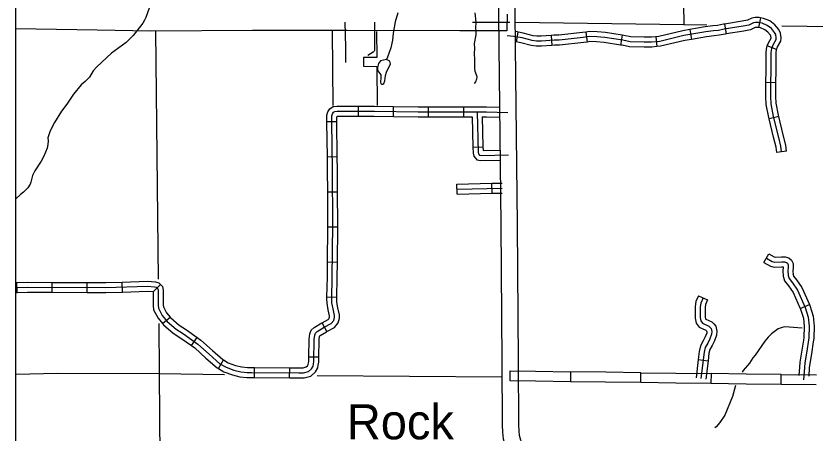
# Model space of a CAD drawing. Extents: x 1373862 to 1376999, y 1168398 to 1170455.
# Drawn here: x 1374675.3 to 1374915.6, y 1169193.7 to 1169319 of the extents above; entities that cross this region are included whole.
import ezdxf

# ---------------------------------------------------------------- set-up
doc = ezdxf.new("R2010")
doc.units = 0
for name, color, linetype in [('Level 10', 7, 'Continuous'), ('Level 25', 7, 'Continuous'), ('Level 31', 7, 'Continuous'), ('Level 32', 7, 'Continuous'), ('Level 34', 7, 'Continuous'), ('Level 35', 7, 'Continuous'), ('Level 45', 7, 'Continuous'), ('Level 5', 7, 'Continuous'), ('Level 6', 7, 'Continuous'), ('R_Draft', 7, 'Continuous')]:
    doc.layers.add(name, color=color, linetype=linetype)

msp = doc.modelspace()

# ---------------------------------------------------------------- linework, layer by layer
at = {"layer": 'Level 10'}
msp.add_line((1374823, 1169319.56), (1374822.98, 1169314.56), dxfattribs=at)
for points in [[(1374818.87, 1169418.56), (1374818.98, 1169414.74), (1374819.85, 1169391.37), (1374819.94, 1169378.37), (1374820.36, 1169342.16), (1374820.46, 1169319.79), (1374820.56, 1169309.87), (1374821.13, 1169256.36), (1374821.44, 1169215.18), (1374821.52, 1169196.04), (1374821.61, 1169193.92), (1374821.82, 1169191.93), (1374822.39, 1169189.89), (1374822.82, 1169188.87), (1374823.6, 1169187.49), (1374824.34, 1169186.4), (1374825.12, 1169185.51), (1374839.88, 1169172.1)], [(1374843.25, 1169175.79), (1374828.68, 1169189.03), (1374828.3, 1169189.47), (1374827.85, 1169190.12), (1374827.32, 1169191.07), (1374827.12, 1169191.55), (1374826.75, 1169192.87), (1374826.6, 1169194.28), (1374826.52, 1169196.16), (1374826.44, 1169215.21), (1374826.13, 1169256.4), (1374825.56, 1169309.92), (1374825.46, 1169319.83), (1374825.36, 1169342.2), (1374824.94, 1169378.41), (1374824.85, 1169391.48), (1374823.98, 1169414.91), (1374823.86, 1169418.72)], [(1374822.98, 1169314.56), (1374808.75, 1169314.61), (1374774.93, 1169314.7), (1374746.42, 1169314.67), (1374715.92, 1169314.49), (1374699.79, 1169314.74), (1374675.34, 1169315.16)]]:
    msp.add_lwpolyline(points, dxfattribs=at)
at = {"layer": 'Level 31'}
for p, q in [((1374823.94, 1169209.31), (1374823.98, 1169212.31)), ((1374842.11, 1169212.08), (1374842.07, 1169209.08)), ((1374863.19, 1169208.8), (1374863.23, 1169211.8)), ((1374884.34, 1169211.53), (1374884.31, 1169208.53)), ((1374905.42, 1169208.26), (1374905.46, 1169211.26)), ((1374884.31, 1169208.53), (1374884.31, 1169208.53))]:
    msp.add_line(p, q, dxfattribs=at)
for points in [[(1374823.98, 1169212.31), (1374831.55, 1169212.21)], [(1374831.55, 1169212.21), (1374842.11, 1169212.08)], [(1374852.67, 1169211.94), (1374842.11, 1169212.08)], [(1374863.23, 1169211.8), (1374852.67, 1169211.94)], [(1374863.23, 1169211.8), (1374873.79, 1169211.67)], [(1374873.79, 1169211.67), (1374884.34, 1169211.53)], [(1374894.9, 1169211.39), (1374884.34, 1169211.53)], [(1374905.46, 1169211.26), (1374894.9, 1169211.39)], [(1374831.51, 1169209.21), (1374823.94, 1169209.31)], [(1374842.07, 1169209.08), (1374831.51, 1169209.21)], [(1374852.63, 1169208.94), (1374842.07, 1169209.08)], [(1374905.46, 1169211.26), (1374916.02, 1169211.12)], [(1374863.19, 1169208.8), (1374852.63, 1169208.94)], [(1374873.75, 1169208.67), (1374863.19, 1169208.8)], [(1374884.31, 1169208.53), (1374873.75, 1169208.67)], [(1374894.86, 1169208.39), (1374884.31, 1169208.53)], [(1374905.42, 1169208.26), (1374894.86, 1169208.39)], [(1374915.98, 1169208.12), (1374905.42, 1169208.26)]]:
    msp.add_lwpolyline(points, dxfattribs=at)
at = {"layer": 'Level 32'}
for p, q in [((1374899.22, 1169318.51), (1374898.61, 1169315.57)), ((1374877.93, 1169314.97), (1374878.45, 1169312.01)), ((1374888.38, 1169316.61), (1374888.86, 1169313.65)), ((1374826.27, 1169314.21), (1374825.69, 1169311.27)), ((1374836.26, 1169313.21), (1374836.5, 1169310.22)), ((1374846.68, 1169314.19), (1374847.09, 1169311.22)), ((1374857.6, 1169313.29), (1374857.15, 1169310.32)), ((1374867.73, 1169312.82), (1374868, 1169309.84)), ((1374904.06, 1169308.99), (1374901.25, 1169310.04)), ((1374903.85, 1169298.97), (1374900.85, 1169299)), ((1374778.29, 1169288.91), (1374778.3, 1169291.91)), ((1374788.83, 1169288.82), (1374788.87, 1169291.82)), ((1374799.4, 1169288.71), (1374799.42, 1169291.71)), ((1374809.97, 1169288.68), (1374809.97, 1169291.68)), ((1374904.69, 1169288.86), (1374901.78, 1169288.15)), ((1374771.84, 1169287.21), (1374768.84, 1169287.21)), ((1374812.75, 1169279.59), (1374815.75, 1169279.66)), ((1374771.96, 1169276.67), (1374768.96, 1169276.63)), ((1374907.05, 1169278.4), (1374904.08, 1169278.02)), ((1374807.98, 1169265.48), (1374807.91, 1169268.48)), ((1374818.54, 1169265.74), (1374818.47, 1169268.74)), ((1374772.06, 1169266.1), (1374769.06, 1169266.08)), ((1374772.12, 1169255.52), (1374769.12, 1169255.55)), ((1374772.01, 1169244.96), (1374769.01, 1169244.99)), ((1374675.7, 1169235.9), (1374675.6, 1169238.9)), ((1374686.2, 1169235.96), (1374686.22, 1169238.96)), ((1374696.76, 1169235.9), (1374696.77, 1169238.9)), ((1374707.37, 1169236.03), (1374707.28, 1169239.03)), ((1374716.68, 1169236.16), (1374718.8, 1169238.28)), ((1374771.79, 1169234.38), (1374768.79, 1169234.46)), ((1374719.43, 1169226.55), (1374721.72, 1169228.49)), ((1374768.77, 1169224.16), (1374767.4, 1169226.83)), ((1374728.1, 1169219.93), (1374729.83, 1169222.38)), ((1374766.43, 1169216.44), (1374763.43, 1169216.47)), ((1374736.24, 1169213.01), (1374737.73, 1169215.62)), ((1374747.07, 1169210.34), (1374747.08, 1169213.34)), ((1374757.63, 1169210.3), (1374757.64, 1169213.3))]:
    msp.add_line(p, q, dxfattribs=at)
for points in [[(1374899.22, 1169318.51), (1374898.77, 1169318.6), (1374897.57, 1169318.6), (1374896.63, 1169318.4), (1374895.25, 1169317.75), (1374893.74, 1169317.48), (1374888.38, 1169316.61)], [(1374904.06, 1169308.99), (1374904.33, 1169309.72), (1374905.36, 1169311.49), (1374905.45, 1169312.52), (1374905.26, 1169313.92), (1374904.71, 1169314.94), (1374903.53, 1169316.39), (1374902, 1169317.54), (1374900.11, 1169318.32), (1374899.22, 1169318.51)], [(1374905.57, 1169278.21), (1374905.35, 1169279.93), (1374904.6, 1169282.93), (1374903.15, 1169288.87), (1374902.44, 1169292.62), (1374902.35, 1169294.82), (1374902.35, 1169298.96), (1374902.4, 1169302.66), (1374902.4, 1169308.03), (1374902.57, 1169309.31), (1374902.97, 1169310.37), (1374903.89, 1169311.95), (1374903.94, 1169312.48), (1374903.81, 1169313.45), (1374903.45, 1169314.11), (1374902.49, 1169315.3), (1374901.25, 1169316.22), (1374899.67, 1169316.88), (1374898.61, 1169317.1), (1374897.73, 1169317.1), (1374897.11, 1169316.97), (1374895.71, 1169316.31), (1374893.99, 1169316), (1374888.31, 1169315.08), (1374886.55, 1169314.73), (1374885.1, 1169314.55), (1374882.76, 1169314.29), (1374876.2, 1169313.14), (1374868.9, 1169311.42), (1374866.48, 1169311.2), (1374864.23, 1169311.16), (1374860, 1169311.25), (1374857.85, 1169311.73), (1374852.39, 1169312.57), (1374850.01, 1169312.74), (1374847.81, 1169312.83), (1374845.87, 1169312.57), (1374838.7, 1169311.78), (1374837.16, 1169311.78), (1374833.33, 1169311.47), (1374831.83, 1169311.47), (1374830.55, 1169311.64), (1374827.52, 1169312.44), (1374825.05, 1169312.92), (1374823.03, 1169313.1)], [(1374877.93, 1169314.97), (1374875.9, 1169314.61), (1374868.66, 1169312.91), (1374867.73, 1169312.82)], [(1374888.38, 1169316.61), (1374888.04, 1169316.55), (1374886.31, 1169316.21), (1374884.92, 1169316.04), (1374882.55, 1169315.77), (1374877.93, 1169314.97)], [(1374898.61, 1169315.57), (1374898.46, 1169315.6), (1374897.89, 1169315.6), (1374897.6, 1169315.54), (1374896.16, 1169314.87), (1374894.24, 1169314.52), (1374888.86, 1169313.65)], [(1374901.25, 1169310.04), (1374901.61, 1169311.01), (1374902.43, 1169312.41), (1374902.43, 1169312.44), (1374902.36, 1169312.98), (1374902.2, 1169313.28), (1374901.44, 1169314.21), (1374900.5, 1169314.91), (1374899.22, 1169315.44), (1374898.61, 1169315.57)], [(1374836.26, 1169313.21), (1374833.27, 1169312.97), (1374831.93, 1169312.97), (1374830.85, 1169313.12), (1374827.85, 1169313.9), (1374825.52, 1169314.36)], [(1374846.68, 1169314.19), (1374845.69, 1169314.06), (1374838.61, 1169313.28), (1374837.1, 1169313.28), (1374836.26, 1169313.21)], [(1374857.6, 1169313.29), (1374852.56, 1169314.06), (1374850.1, 1169314.24), (1374847.74, 1169314.34), (1374846.68, 1169314.19)], [(1374867.73, 1169312.82), (1374866.39, 1169312.7), (1374864.23, 1169312.66), (1374860.19, 1169312.74), (1374858.13, 1169313.21), (1374857.6, 1169313.29)], [(1374888.86, 1169313.65), (1374888.58, 1169313.6), (1374886.79, 1169313.24), (1374885.27, 1169313.06), (1374882.98, 1169312.8), (1374878.45, 1169312.01)], [(1374836.5, 1169310.22), (1374833.39, 1169309.97), (1374831.73, 1169309.97), (1374830.26, 1169310.17), (1374827.18, 1169310.97), (1374825.69, 1169311.27)], [(1374847.09, 1169311.22), (1374846.06, 1169311.08), (1374838.78, 1169310.28), (1374837.22, 1169310.28), (1374836.5, 1169310.22)], [(1374857.15, 1169310.32), (1374852.22, 1169311.08), (1374849.93, 1169311.25), (1374847.88, 1169311.33), (1374847.09, 1169311.22)], [(1374868, 1169309.84), (1374866.56, 1169309.7), (1374864.23, 1169309.66), (1374859.82, 1169309.75), (1374857.57, 1169310.26), (1374857.15, 1169310.32)], [(1374878.45, 1169312.01), (1374876.5, 1169311.67), (1374869.14, 1169309.94), (1374868, 1169309.84)], [(1374900.85, 1169299), (1374900.9, 1169302.67), (1374900.9, 1169308.13), (1374901.11, 1169309.68), (1374901.25, 1169310.04)], [(1374903.85, 1169298.97), (1374903.9, 1169302.65), (1374903.9, 1169307.93), (1374904.04, 1169308.94), (1374904.06, 1169308.99)], [(1374901.78, 1169288.15), (1374901.68, 1169288.56), (1374900.95, 1169292.45), (1374900.85, 1169294.79), (1374900.85, 1169298.97), (1374900.85, 1169299)], [(1374904.69, 1169288.86), (1374904.61, 1169289.19), (1374903.94, 1169292.79), (1374903.85, 1169294.85), (1374903.85, 1169298.95), (1374903.85, 1169298.97)], [(1374768.84, 1169287.21), (1374768.84, 1169289.2), (1374769.15, 1169290.26), (1374769.7, 1169291.17), (1374770.71, 1169291.82), (1374771.83, 1169291.94), (1374778.3, 1169291.91)], [(1374778.3, 1169291.91), (1374783.11, 1169291.9), (1374788.87, 1169291.82)], [(1374788.87, 1169291.82), (1374796.28, 1169291.73), (1374799.42, 1169291.71)], [(1374799.42, 1169291.71), (1374804.39, 1169291.68), (1374809.97, 1169291.68)], [(1374809.97, 1169291.68), (1374816.81, 1169291.68), (1374820.75, 1169291.59)], [(1374675.34, 1169237.39), (1374678.75, 1169237.5), (1374702.33, 1169237.37), (1374714.86, 1169237.77), (1374717, 1169237.64), (1374717.49, 1169237.47), (1374717.98, 1169236.98), (1374718.11, 1169236.46), (1374718.11, 1169232.08), (1374718.18, 1169231.17), (1374719.31, 1169229), (1374720.82, 1169227.23), (1374723.47, 1169224.89), (1374725.74, 1169223.44), (1374730.02, 1169220.41), (1374733.42, 1169217.33), (1374736.67, 1169214.5), (1374738.51, 1169213.44), (1374740.85, 1169212.56), (1374742.94, 1169212.04), (1374744.84, 1169211.82), (1374746.14, 1169211.84), (1374760.39, 1169211.79), (1374761.84, 1169211.79), (1374763.3, 1169212.14), (1374764.21, 1169212.95), (1374764.65, 1169213.76), (1374764.75, 1169214.33), (1374764.92, 1169215.14), (1374764.99, 1169221.75), (1374765.17, 1169223.08), (1374765.39, 1169223.72), (1374765.88, 1169224.22), (1374768, 1169225.45), (1374770.16, 1169226.56), (1374770.88, 1169227.44), (1374771.12, 1169228.38), (1374771.12, 1169229.04), (1374770.68, 1169230.97), (1374770.36, 1169232.82), (1374770.29, 1169234.08), (1374770.46, 1169240.46), (1374770.63, 1169256.39), (1374770.51, 1169272.81), (1374770.34, 1169287.11), (1374770.34, 1169288.98), (1374770.53, 1169289.65), (1374770.8, 1169290.09), (1374771.22, 1169290.36), (1374771.91, 1169290.44), (1374783.1, 1169290.4), (1374796.26, 1169290.23), (1374804.39, 1169290.18), (1374816.79, 1169290.18), (1374823.27, 1169290.03)], [(1374771.84, 1169287.21), (1374771.84, 1169288.77), (1374771.88, 1169288.93), (1374771.99, 1169288.94), (1374778.29, 1169288.91)], [(1374778.29, 1169288.91), (1374783.09, 1169288.9), (1374788.83, 1169288.82)], [(1374788.83, 1169288.82), (1374796.25, 1169288.73), (1374799.4, 1169288.71)], [(1374799.4, 1169288.71), (1374804.38, 1169288.68), (1374809.97, 1169288.68)], [(1374809.97, 1169288.68), (1374812.54, 1169288.68)], [(1374812.54, 1169288.68), (1374812.75, 1169279.59)], [(1374814, 1169290.18), (1374814.29, 1169277.97), (1374814.39, 1169277.59), (1374814.72, 1169277.21), (1374815.25, 1169277.11), (1374823.41, 1169277.25)], [(1374815.54, 1169288.68), (1374815.75, 1169279.66)], [(1374815.54, 1169288.68), (1374816.77, 1169288.68), (1374820.78, 1169288.59)], [(1374907.05, 1169278.4), (1374906.82, 1169280.21), (1374906.05, 1169283.29), (1374904.69, 1169288.86)], [(1374768.96, 1169276.63), (1374768.84, 1169287.1), (1374768.84, 1169287.21)], [(1374771.96, 1169276.67), (1374771.84, 1169287.12), (1374771.84, 1169287.21)], [(1374904.08, 1169278.02), (1374903.87, 1169279.65), (1374903.14, 1169282.57), (1374901.78, 1169288.15)], [(1374812.75, 1169279.59), (1374812.79, 1169277.77), (1374813.02, 1169276.87), (1374813.94, 1169275.82), (1374815.12, 1169275.61), (1374820.92, 1169275.71)], [(1374815.75, 1169279.66), (1374815.78, 1169278.62), (1374820.89, 1169278.71)], [(1374769.06, 1169266.08), (1374769.01, 1169272.79), (1374768.96, 1169276.63)], [(1374772.06, 1169266.1), (1374772.01, 1169272.82), (1374771.96, 1169276.67)], [(1374807.91, 1169268.48), (1374818.47, 1169268.74)], [(1374807.95, 1169266.98), (1374821.53, 1169267.31)], [(1374818.47, 1169268.74), (1374821.49, 1169268.81)], [(1374769.12, 1169255.55), (1374769.13, 1169256.4), (1374769.06, 1169266.08)], [(1374772.12, 1169255.52), (1374772.13, 1169256.39), (1374772.06, 1169266.1)], [(1374807.98, 1169265.48), (1374818.54, 1169265.74)], [(1374818.54, 1169265.74), (1374821.57, 1169265.81)], [(1374769.01, 1169244.99), (1374769.12, 1169255.55)], [(1374772.01, 1169244.96), (1374772.12, 1169255.52)], [(1374768.79, 1169234.46), (1374768.96, 1169240.49), (1374769.01, 1169244.99)], [(1374771.79, 1169234.38), (1374771.96, 1169240.43), (1374772.01, 1169244.96)], [(1374675.34, 1169238.89), (1374675.6, 1169238.9)], [(1374675.6, 1169238.9), (1374678.73, 1169239), (1374686.22, 1169238.96)], [(1374686.22, 1169238.96), (1374696.77, 1169238.9)], [(1374696.77, 1169238.9), (1374702.31, 1169238.87), (1374707.28, 1169239.03)], [(1374707.28, 1169239.03), (1374714.88, 1169239.27), (1374717.3, 1169239.13), (1374718.31, 1169238.77), (1374718.8, 1169238.28)], [(1374718.8, 1169238.28), (1374719.35, 1169237.74), (1374719.61, 1169236.64), (1374719.61, 1169232.14), (1374719.65, 1169231.59), (1374720.57, 1169229.84), (1374721.72, 1169228.49)], [(1374675.34, 1169235.89), (1374675.7, 1169235.9)], [(1374675.7, 1169235.9), (1374678.77, 1169236), (1374686.2, 1169235.96)], [(1374686.2, 1169235.96), (1374696.76, 1169235.9)], [(1374696.76, 1169235.9), (1374702.35, 1169235.87), (1374707.37, 1169236.03)], [(1374707.37, 1169236.03), (1374714.84, 1169236.27), (1374716.68, 1169236.16), (1374716.68, 1169236.16)], [(1374716.61, 1169236.24), (1374716.61, 1169232.02), (1374716.71, 1169230.74), (1374718.06, 1169228.16), (1374719.43, 1169226.55)], [(1374767.4, 1169226.83), (1374769.19, 1169227.75), (1374769.51, 1169228.13), (1374769.62, 1169228.57), (1374769.62, 1169228.87), (1374769.21, 1169230.68), (1374768.87, 1169232.65), (1374768.78, 1169234.05), (1374768.79, 1169234.46)], [(1374768.77, 1169224.16), (1374771.13, 1169225.37), (1374772.24, 1169226.75), (1374772.62, 1169228.18), (1374772.62, 1169229.21), (1374772.15, 1169231.27), (1374771.85, 1169232.99), (1374771.79, 1169234.1), (1374771.79, 1169234.38)], [(1374721.72, 1169228.49), (1374721.89, 1169228.28), (1374724.38, 1169226.09), (1374726.58, 1169224.68), (1374729.83, 1169222.38)], [(1374719.43, 1169226.55), (1374719.74, 1169226.17), (1374722.57, 1169223.69), (1374724.9, 1169222.19), (1374728.1, 1169219.93)], [(1374763.43, 1169216.47), (1374763.49, 1169221.86), (1374763.7, 1169223.43), (1374764.08, 1169224.54), (1374764.96, 1169225.42), (1374767.28, 1169226.76), (1374767.4, 1169226.83)], [(1374766.43, 1169216.44), (1374766.49, 1169221.65), (1374766.63, 1169222.74), (1374766.69, 1169222.91), (1374766.8, 1169223.02), (1374768.72, 1169224.13), (1374768.77, 1169224.16)], [(1374729.83, 1169222.38), (1374730.96, 1169221.58), (1374734.41, 1169218.45), (1374737.54, 1169215.73), (1374737.73, 1169215.62)], [(1374728.1, 1169219.93), (1374729.08, 1169219.24), (1374732.42, 1169216.21), (1374735.79, 1169213.27), (1374736.24, 1169213.01)], [(1374757.63, 1169210.3), (1374760.39, 1169210.29), (1374762.02, 1169210.29), (1374764.01, 1169210.77), (1374765.4, 1169212.01), (1374766.08, 1169213.26), (1374766.22, 1169214.05), (1374766.42, 1169214.98), (1374766.43, 1169216.44)], [(1374757.64, 1169213.3), (1374760.39, 1169213.29), (1374761.67, 1169213.29), (1374762.58, 1169213.51), (1374763.01, 1169213.9), (1374763.21, 1169214.26), (1374763.27, 1169214.61), (1374763.42, 1169215.31), (1374763.43, 1169216.47)], [(1374737.73, 1169215.62), (1374739.15, 1169214.8), (1374741.3, 1169213.99), (1374743.21, 1169213.52), (1374744.91, 1169213.32), (1374746.13, 1169213.34), (1374747.08, 1169213.34)], [(1374736.24, 1169213.01), (1374737.87, 1169212.08), (1374740.4, 1169211.12), (1374742.67, 1169210.56), (1374744.76, 1169210.32), (1374746.15, 1169210.34), (1374747.07, 1169210.34)], [(1374747.08, 1169213.34), (1374757.64, 1169213.3)], [(1374747.07, 1169210.34), (1374757.63, 1169210.3)]]:
    msp.add_lwpolyline(points, dxfattribs=at)
at = {"layer": 'Level 34'}
for points in [[(1374774.19, 1169317.2), (1374774.4, 1169309.66), (1374774.43, 1169305.06)], [(1374783.12, 1169317.18), (1374783.15, 1169308.71), (1374783.08, 1169308.47), (1374782.78, 1169308.16), (1374781.14, 1169307.14)]]:
    msp.add_lwpolyline(points, dxfattribs=at)
at = {"layer": 'Level 35'}
for points in [[(1374716.02, 1169323.13), (1374714.41, 1169318.57), (1374713.99, 1169317.8), (1374713.46, 1169316.92), (1374710.54, 1169313.15), (1374708.47, 1169311.05), (1374704.09, 1169307.88), (1374699.6, 1169303.79), (1374698.57, 1169302.52), (1374697.44, 1169300.66), (1374696.17, 1169299.34), (1374694.9, 1169298.35), (1374692.65, 1169295.52), (1374690.65, 1169292.54), (1374689.07, 1169290.39), (1374686.96, 1169286.98), (1374685.58, 1169284.49), (1374684.93, 1169282.45), (1374685.04, 1169281.55), (1374684.95, 1169280.37), (1374684.74, 1169279.26), (1374683.68, 1169276.86), (1374682.88, 1169275.43), (1374680.97, 1169272.45), (1374680.27, 1169271.11), (1374679.84, 1169269.09), (1374679.58, 1169268.45), (1374678.91, 1169267.42), (1374677.56, 1169266.12), (1374676.66, 1169265.42), (1374675.34, 1169264.02)], [(1374790.15, 1169319.96), (1374789.36, 1169317.29), (1374788.75, 1169313.84), (1374788.58, 1169311.77), (1374788.06, 1169309.45), (1374787.05, 1169306.63), (1374786.75, 1169305.94), (1374784.92, 1169305.61), (1374784.34, 1169304.73), (1374784.05, 1169303.58), (1374784.03, 1169302.84), (1374784.16, 1169302.52), (1374785.03, 1169301.4), (1374785.07, 1169300.58), (1374784.91, 1169299.19), (1374785.04, 1169298.79), (1374785.24, 1169298.58), (1374785.6, 1169298.57), (1374785.9, 1169298.78), (1374786.22, 1169299.59), (1374786.42, 1169301.12), (1374786.77, 1169302.11), (1374787.93, 1169304.67), (1374787.8, 1169305.49), (1374786.75, 1169305.94)], [(1374813.29, 1169319.99), (1374813.64, 1169317.22), (1374813.55, 1169315.39)], [(1374813.55, 1169315.39), (1374813.63, 1169314.45), (1374813.58, 1169313.34), (1374813.11, 1169310.78), (1374813.21, 1169309.28), (1374813.11, 1169307.73), (1374813.23, 1169305.95), (1374813.24, 1169303.36), (1374813.33, 1169302.48), (1374813.82, 1169301.17), (1374813.91, 1169300.69), (1374813.81, 1169300.05), (1374813.55, 1169299.26), (1374813.11, 1169298.73)], [(1374911.78, 1169225.17), (1374906.48, 1169225.55), (1374905.71, 1169225.41), (1374904.48, 1169224.94), (1374902.52, 1169223.46), (1374901.5, 1169222.47), (1374900.56, 1169221.24), (1374897.62, 1169217.05), (1374896.88, 1169216.31), (1374895.89, 1169214.7), (1374894.02, 1169212.5), (1374893.67, 1169211.94)], [(1374891.66, 1169207.93), (1374890.81, 1169204.59), (1374888.53, 1169199.03), (1374887.03, 1169196.82), (1374885.85, 1169195.51), (1374885.43, 1169195.26)]]:
    msp.add_lwpolyline(points, dxfattribs=at)
at = {"layer": 'Level 45'}
for p, q in [((1374900.24, 1169244.94), (1374901.74, 1169247.54)), ((1374880.56, 1169234.9), (1374883.29, 1169233.66)), ((1374911.17, 1169231.08), (1374913.92, 1169232.29)), ((1374880.47, 1169215.73), (1374883.45, 1169215.38))]:
    msp.add_line(p, q, dxfattribs=at)
for points in [[(1374901.74, 1169247.54), (1374903.32, 1169246.63), (1374903.62, 1169246.55), (1374905.55, 1169246.59), (1374906.59, 1169246.65), (1374907.72, 1169246.3), (1374908.49, 1169245.64), (1374908.99, 1169244.64), (1374909.05, 1169243.34), (1374908.96, 1169242.46), (1374909.03, 1169241.26), (1374909.01, 1169241.34)], [(1374900.99, 1169246.24), (1374902.75, 1169245.22), (1374903.45, 1169245.05), (1374905.61, 1169245.09), (1374906.4, 1169245.14), (1374906.98, 1169244.96), (1374907.28, 1169244.7), (1374907.5, 1169244.26), (1374907.55, 1169243.37), (1374907.46, 1169242.49), (1374907.55, 1169241), (1374907.81, 1169240.12), (1374908.87, 1169238.79), (1374910.37, 1169236.64), (1374912.65, 1169231.44), (1374913.58, 1169228.53), (1374913.84, 1169225.76), (1374913.75, 1169222.26), (1374913.05, 1169217.68), (1374912.52, 1169214.77), (1374912.39, 1169213.36), (1374912.17, 1169209.67)], [(1374900.24, 1169244.94), (1374902.18, 1169243.82), (1374903.28, 1169243.54), (1374905.67, 1169243.59), (1374906.03, 1169243.61), (1374906.04, 1169243.41), (1374905.96, 1169242.52), (1374906.06, 1169240.73), (1374906.14, 1169240.48)], [(1374906.14, 1169240.48), (1374906.46, 1169239.41), (1374907.66, 1169237.9), (1374909.05, 1169235.9), (1374911.17, 1169231.08)], [(1374909.01, 1169241.34), (1374909.17, 1169240.82), (1374910.07, 1169239.69), (1374911.68, 1169237.37), (1374913.92, 1169232.29)], [(1374880.56, 1169234.9), (1374879.77, 1169233.17), (1374879.55, 1169231.66), (1374879.55, 1169228.22), (1374879.87, 1169226.72), (1374880.8, 1169225.49), (1374882.8, 1169224.58), (1374882.95, 1169224.42)], [(1374881.93, 1169234.28), (1374881.22, 1169232.74), (1374881.05, 1169231.55), (1374881.05, 1169228.38), (1374881.27, 1169227.36), (1374881.77, 1169226.7), (1374883.69, 1169225.82), (1374884.39, 1169225.07), (1374884.57, 1169224.15), (1374884.52, 1169223.4), (1374883.99, 1169221.96), (1374883.34, 1169220.67), (1374882.59, 1169219.35), (1374882.23, 1169217.94), (1374881.31, 1169210.07)], [(1374883.29, 1169233.66), (1374882.67, 1169232.31), (1374882.55, 1169231.44), (1374882.55, 1169228.54), (1374882.66, 1169228.01), (1374882.74, 1169227.9), (1374884.58, 1169227.07), (1374885.13, 1169226.48)], [(1374911.17, 1169231.08), (1374911.25, 1169230.91), (1374912.1, 1169228.23), (1374912.34, 1169225.7), (1374912.26, 1169222.39), (1374912.13, 1169221.54)], [(1374913.92, 1169232.29), (1374914.06, 1169231.97), (1374915.06, 1169228.83), (1374915.34, 1169225.81), (1374915.25, 1169222.12), (1374915.09, 1169221.09)], [(1374885.13, 1169226.48), (1374885.78, 1169225.78), (1374886.08, 1169224.25), (1374886.01, 1169223.09), (1374885.37, 1169221.36), (1374884.66, 1169219.96), (1374883.99, 1169218.79), (1374883.71, 1169217.67), (1374883.45, 1169215.38)], [(1374882.95, 1169224.42), (1374883, 1169224.36), (1374883.06, 1169224.05), (1374883.04, 1169223.71), (1374882.62, 1169222.56), (1374882.01, 1169221.38), (1374881.18, 1169219.91), (1374880.76, 1169218.21), (1374880.47, 1169215.73)], [(1374912.13, 1169221.54), (1374911.57, 1169217.92), (1374911.03, 1169214.97), (1374910.89, 1169213.47), (1374910.74, 1169210.95)], [(1374915.09, 1169221.09), (1374914.53, 1169217.43), (1374914.01, 1169214.56), (1374913.89, 1169213.24), (1374913.74, 1169210.77)], [(1374880.47, 1169215.73), (1374879.82, 1169210.24)], [(1374883.45, 1169215.38), (1374882.8, 1169209.89)]]:
    msp.add_lwpolyline(points, dxfattribs=at)
at = {"layer": 'Level 5'}
for points in [[(1374823.8, 1169317.07), (1374812.58, 1169317.1)], [(1374883.07, 1169316.3), (1374876.2, 1169316.39)], [(1374928.6, 1169315.72), (1374905.58, 1169316.01)], [(1374717.26, 1169314.49), (1374718.1, 1169239.87)], [(1374718.25, 1169226.6), (1374718.41, 1169211.53)], [(1374675.34, 1169211.4), (1374687.84, 1169211.69), (1374718.41, 1169211.53)], [(1374718.41, 1169211.53), (1374719.1, 1169122.68)], [(1374718.41, 1169211.53), (1374738.04, 1169211.23)], [(1374765.87, 1169210.95), (1374821.46, 1169210.52)]]:
    msp.add_lwpolyline(points, dxfattribs=at)
at = {"layer": 'Level 6'}
for points in [[(1374874.03, 1169447.39), (1374876.2, 1169316.39), (1374825.49, 1169317.04)], [(1374770.71, 1169292.17), (1374770.53, 1169314.51)], [(1374783.74, 1169314.41), (1374783.8, 1169306.53), (1374779.84, 1169306.55), (1374779.86, 1169303.91), (1374783.82, 1169303.89), (1374783.91, 1169292.17)]]:
    msp.add_lwpolyline(points, dxfattribs=at)
at = {"layer": 'R_Draft'}
msp.add_lwpolyline([(1374675.34, 1169579.43), (1376182.76, 1169579.43), (1376182.76, 1168562.99), (1374675.34, 1168562.99)], close=True, dxfattribs=at)

# ---------------------------------------------------------------- texts
at = {"layer": 'Level 25'}
msp.add_text('Rock', height=10.56, dxfattribs=at).set_placement((1374774.84, 1169191.76))

doc.saveas('drawing.dxf')
